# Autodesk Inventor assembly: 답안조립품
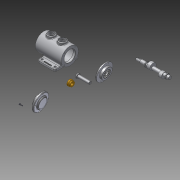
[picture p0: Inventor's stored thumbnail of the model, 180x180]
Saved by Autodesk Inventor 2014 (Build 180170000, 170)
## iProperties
Created: 2014-12
Part Number: 답안조립품
Document SubType Name: Assembly
Designer: Owner
Author: Owner
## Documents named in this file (10)
- C:\Users\Owner\Desktop\441223V1016\답안조립품.iam
- C:\Users\Owner\Desktop\441223V1016\본체.ipt
- C:\Users\Owner\Desktop\441223V1016\M4-소켓머리.ipt
- C:\Users\Owner\Desktop\441223V1016\뒷커버.ipt
- C:\Users\Owner\Desktop\441223V1016\베어링 6203.ipt
- C:\Users\Owner\Desktop\441223V1016\부시.ipt
- C:\Users\Owner\Desktop\441223V1016\슬라이더.ipt
- C:\Users\Owner\Desktop\441223V1016\앞커버.ipt
- C:\Users\Owner\Desktop\441223V1016\오일실.ipt
- C:\Users\Owner\Desktop\441223V1016\축.ipt
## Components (4 placed, 3 different names)
1. 9-M4-소켓머리:1
2. 7-베어링 6203:1
3. 8-오일실:1
4. 7-베어링 6203:2
